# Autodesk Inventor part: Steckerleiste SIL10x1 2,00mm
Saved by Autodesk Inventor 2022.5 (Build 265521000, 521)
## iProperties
Created: 2024-12
Part Number: Steckerleiste SIL10x1 2,00mm
Material: Generic
Document SubType Name: Modeling
Designer: AdminForWorker
Density: 1 g/cm^3
Appearance: Default
Title: Steckerleiste SIL10x1 2,00mm
Author: AdminForWorker
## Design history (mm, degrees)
feature "Body1"
body "Solid1"
